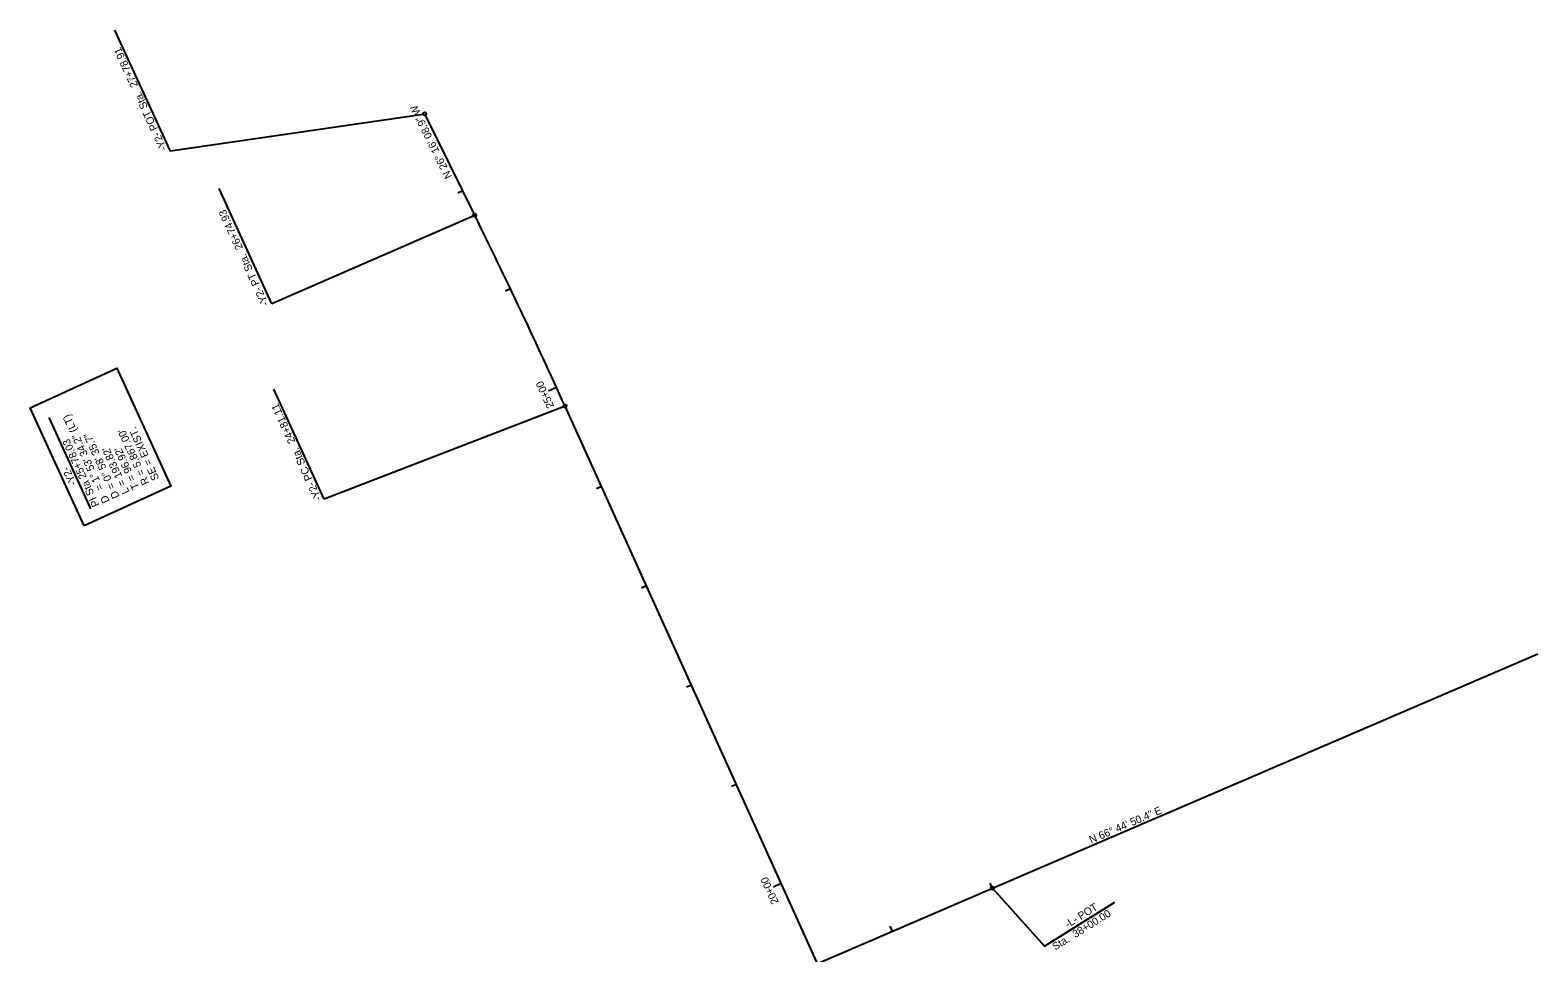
# Model space of a CAD drawing. Extents: x 2045940 to 2048976, y 757914 to 760106.
# Drawn here: x 2047592 to 2048976, y 759259 to 760106 of the extents above; entities that cross this region are included whole.
import ezdxf

# ---------------------------------------------------------------- set-up
doc = ezdxf.new("R2010")
doc.units = 0
for name, color, linetype in [('Prop AutoTurn Projected Path', 7, 'Continuous'), ('Prop Conc 1ft 6in Curb and Gutter', 7, 'Continuous'), ('Prop Conc 5in Monolithic Surface Mount Island', 7, 'Continuous'), ('Prop Dimension', 7, 'Continuous'), ('Prop Horizontal Alignment', 7, 'Continuous'), ('Prop Lane Lines', 7, 'Continuous'), ('Prop Superelevation Label', 7, 'Continuous'), ('Prop Terminator CELL', 7, 'Continuous')]:
    doc.layers.add(name, color=color, linetype=linetype)

msp = doc.modelspace()

# ---------------------------------------------------------------- linework, layer by layer
at = {"layer": 'Prop AutoTurn Projected Path'}
msp.add_line((2047647.5, 759666.6), (2047609, 759750.6), dxfattribs=at)
at = {"layer": 'Prop Conc 1ft 6in Curb and Gutter'}
for p, q in [((2047720.4, 759995.1), (2047669.5, 760106.2)), ((2047952.5, 760028.7), (2047720.4, 759995.1)), ((2047813.6, 759855), (2047765.1, 759960.9)), ((2047998.5, 759935.5), (2047813.6, 759855)), ((2047861.7, 759675.6), (2047815.5, 759776.5)), ((2048081.4, 759760.3), (2047861.7, 759675.6)), ((2048475.2, 759318.5), (2048523.1, 759265.4)), ((2048523.1, 759265.4), (2048587.6, 759305.6))]:
    msp.add_line(p, q, dxfattribs=at)
for centre in [(2047953.9, 760029.4), (2047999.9, 759936.2), (2048082.8, 759761), (2048475.2, 759318.5)]:
    msp.add_circle(centre, 1.5, dxfattribs=at)
at = {"layer": 'Prop Dimension'}
for p, q in [((2048074.9, 759778.2), (2048067.7, 759774.8)), ((2048281.3, 759322.7), (2048274.1, 759319.4))]:
    msp.add_line(p, q, dxfattribs=at)
at = {"layer": 'Prop Horizontal Alignment'}
for p, q in [((2047999.9, 759936.2), (2047953.9, 760029.4)), ((2048694.1, 758411.9), (2048082.8, 759761)), ((2047919.3, 759079.6), (2048475.2, 759318.5))]:
    msp.add_line(p, q, dxfattribs=at)
msp.add_lwpolyline([(2048475.2, 759318.5), (2048976, 759533.7)], dxfattribs=at)
msp.add_arc((2042738.8, 757339.5), 5867, 24.37631, 26.26914, dxfattribs=at)
msp.add_arc((2042738.8, 757339.5), 5867, 24.37631, 26.26914, dxfattribs=at)
at = {"layer": 'Prop Superelevation Label'}
msp.add_lwpolyline([(2047641.2, 759651.1), (2047591.6, 759759.4), (2047671.3, 759795.9), (2047720.9, 759687.6)], close=True, dxfattribs=at)
at = {"layer": 'Prop Terminator CELL'}
for p, q in [((2047988.8, 759958.6), (2047984.3, 759956.4)), ((2048032.6, 759868.8), (2048028.1, 759866.6)), ((2048116.2, 759687.1), (2048111.7, 759685)), ((2048157.5, 759596), (2048153, 759593.9)), ((2048198.8, 759504.9), (2048194.2, 759502.9)), ((2048240.1, 759413.8), (2048235.5, 759411.8)), ((2048475.2, 759318.5), (2048473.2, 759323.1)), ((2048383.3, 759279), (2048381.3, 759283.6))]:
    msp.add_line(p, q, dxfattribs=at)

# ---------------------------------------------------------------- texts
at = {"layer": 'Prop AutoTurn Projected Path'}
for s, p in [('= 1%%d 53\' 34.2" (LT)', (2047659.2, 759685.4)), ("R = 5,867.00'", (2047701.2, 759690.5)), ('SE = EXIST.', (2047710.3, 759694.6)), ('PI Sta 25+78.03', (2047655.4, 759670.3)), ('D = 0%%d 58\' 35.7"', (2047673.9, 759678)), ("L = 193.82'", (2047683, 759682.2)), ("T = 96.92'", (2047692.1, 759686.3)), ('-Y2-', (2047634.4, 759689.9)), ('D', (2047664.8, 759673.8))]:
    msp.add_text(s, height=7, rotation=114.6102, dxfattribs=at).set_placement(p)
at = {"layer": 'Prop Conc 1ft 6in Curb and Gutter'}
for s, rotation, p in [('-Y2- POT Sta.  27+78.91', 114.6102, (2047717.5, 759997.2)), ('-Y2- PT Sta.  26+74.93', 114.6102, (2047810.8, 759854.8)), ('-Y2- PC Sta.  24+81.11', 114.6102, (2047859.5, 759675.9)), ('Sta.  38+00.00', 31.9109, (2048532.8, 759261.1)), ('-L- POT ', 31.9109, (2048544.4, 759281.7))]:
    msp.add_text(s, height=7, rotation=rotation, dxfattribs=at).set_placement(p)
at = {"layer": 'Prop Conc 5in Monolithic Surface Mount Island'}
for s, rotation, p in [('25+00', 114.5608, (2048072.9, 759760.9)), ('20+00', 114.3763, (2048279.2, 759305.6))]:
    msp.add_text(s, height=7, rotation=rotation, dxfattribs=at).set_placement(p)
at = {"layer": 'Prop Lane Lines'}
for s, rotation, p in [('N 26%%d 16\' 08.9" W', 116.2691, (2047979.2, 759971.8)), ('N 66%%d 44\' 50.4" E', 23.2527, (2048565.9, 759359.3))]:
    msp.add_text(s, height=7, rotation=rotation, dxfattribs=at).set_placement(p)

doc.saveas('drawing.dxf')
